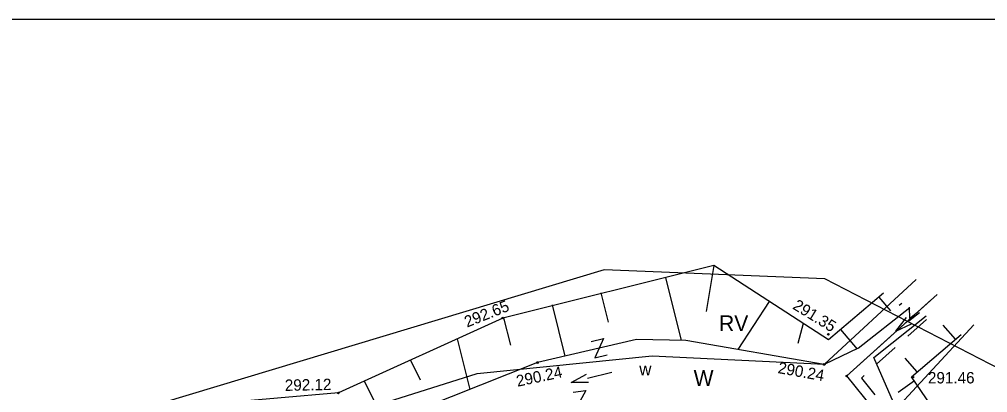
# Model space of a CAD drawing. Extents: x 7477803 to 7478145, y 5500698 to 5500984.
# Drawn here: x 7477935.9 to 7477993.7, y 5500961.3 to 5500983.6 of the extents above; entities that cross this region are included whole.
import ezdxf

# ---------------------------------------------------------------- set-up
doc = ezdxf.new("R2010")
doc.units = 0
for name, color, linetype in [('203-Punkt załamania granicy działki nie stabilizowany', 7, 'Continuous'), ('gr_dzialki', 7, 'Continuous'), ('gr_klasy', 7, 'Continuous'), ('gr_uzytek', 7, 'Continuous'), ('nazwa_cieku', 7, 'Continuous'), ('opis_klasy', 7, 'Continuous'), ('opis_uzytek', 7, 'Continuous'), ('pkt_wys', 7, 'Continuous'), ('pob_gr_obrebu', 7, 'Continuous'), ('przehaczenie', 7, 'Continuous'), ('robocza11', 7, 'Continuous'), ('rzeka', 7, 'Continuous'), ('skarp_wypel', 7, 'Continuous'), ('skarpa_gora', 7, 'Continuous'), ('zakresy', 7, 'Continuous')]:
    doc.layers.add(name, color=color, linetype=linetype)

# ---------------------------------------------------------------- blocks, each defined once
blk = doc.blocks.new('203')
blk.add_circle((0, 0), 0.045)
blk = doc.blocks.new('993')
at = {"layer": 'nazwa_cieku'}
for p, q in [((0, 0), (1.5, 0)), ((1.5, 0.25), (2.5, 0)), ((2.5, 0), (1.5, -0.25))]:
    blk.add_line(p, q, dxfattribs=at)
blk = doc.blocks.new('801_3')
at = {"layer": 'pkt_wys'}
blk.add_circle((0, 0), 0.045, dxfattribs=at)
blk.add_circle((0, 0), 0.045, dxfattribs=at)
blk = doc.blocks.new('801_5')
at = {"layer": 'pkt_wys'}
blk.add_circle((0, 0), 0.05, dxfattribs=at)
blk.add_circle((0, 0), 0.05, dxfattribs=at)
blk = doc.blocks.new('991_5_1')
at = {"layer": 'przehaczenie'}
blk.add_lwpolyline([(-0.38, 0.5), (0.38, 0.5), (-0.38, -0.5), (0.38, -0.5)], dxfattribs=at)

msp = doc.modelspace()

# ---------------------------------------------------------------- linework, layer by layer
at = {"layer": 'gr_dzialki'}
for points in [[(7477990.325, 5500966.847), (7477985.26, 5500962.28)], [(7477986.83, 5500960.33), (7477985.26, 5500962.28)]]:
    msp.add_lwpolyline(points, dxfattribs=at)
at = {"layer": 'gr_klasy'}
for points in [[(7477983.93, 5500962.98), (7477989.394, 5500968.04)], [(7477992.835, 5500965.322), (7477987.47, 5500959.53)], [(7477963.19, 5500962.42), (7477973.64, 5500963.49)], [(7477973.64, 5500963.49), (7477983.93, 5500962.98)], [(7477939.89, 5500955.07), (7477963.19, 5500962.42)]]:
    msp.add_lwpolyline(points, dxfattribs=at)
at = {"layer": 'gr_uzytek'}
msp.add_lwpolyline([(7477986.83, 5500960.33), (7477985.26, 5500962.28), (7477990.655, 5500967.144)], dxfattribs=at)
at = {"layer": 'nazwa_cieku'}
for p, q in [((7477988.182, 5500964.963), (7477988.816, 5500965.776)), ((7477988.97, 5500965.579), (7477989.596, 5500966.069)), ((7477988.182, 5500964.963), (7477989.124, 5500965.382))]:
    msp.add_line(p, q, dxfattribs=at)
at = {"layer": 'pob_gr_obrebu'}
for p, q in [((7477990.013, 5500965.654), (7477988.898, 5500964.65)), ((7477988.155, 5500963.98), (7477987.041, 5500962.976))]:
    msp.add_line(p, q, dxfattribs=at)
msp.add_lwpolyline([(7477986.298, 5500962.306), (7477986.13, 5500962.155), (7477986.928, 5500961.162)], dxfattribs=at)
at = {"layer": 'przehaczenie'}
for points in [[(7477988.382, 5500966.499), (7477988.545, 5500966.628)], [(7477988.989, 5500966.391), (7477989.002, 5500965.715), (7477989.509, 5500966.115)]]:
    msp.add_lwpolyline(points, dxfattribs=at)
at = {"layer": 'robocza11'}
msp.add_lwpolyline([(7478014.996, 5500697.565), (7478144.729, 5500697.565), (7478144.729, 5500983.565), (7477803.256, 5500983.565), (7477803.256, 5500697.565), (7478010.821, 5500697.565)], close=True, dxfattribs=at)
at = {"layer": 'rzeka'}
for points in [[(7477985.943, 5500963.933), (7477989.027, 5500966.371)], [(7477986.866, 5500963.388), (7477989.991, 5500965.859)], [(7477985.943, 5500963.933), (7477983.914, 5500962.968), (7477975.662, 5500964.399), (7477972.702, 5500964.466), (7477966.794, 5500963.08), (7477958.237, 5500959.69)], [(7477990.994, 5500955.223), (7477989.636, 5500957.056), (7477986.866, 5500963.388)]]:
    msp.add_lwpolyline(points, dxfattribs=at)
at = {"layer": 'skarp_wypel'}
for p, q in [((7477977.317, 5500968.871), (7477976.87, 5500966.13)), ((7477974.444, 5500968.156), (7477975.377, 5500964.406)), ((7477970.587, 5500967.249), (7477971.027, 5500965.485)), ((7477980.619, 5500966.734), (7477978.76, 5500963.862)), ((7477987.169, 5500966.987), (7477987.864, 5500966.167)), ((7477967.676, 5500966.523), (7477968.439, 5500963.466)), ((7477964.776, 5500965.751), (7477965.186, 5500964.109)), ((7477982.649, 5500965.421), (7477982.346, 5500964.221)), ((7477984.881, 5500965.046), (7477985.873, 5500963.878)), ((7477991.741, 5500964.467), (7477991.02, 5500965.311)), ((7477961.998, 5500964.496), (7477962.751, 5500961.478)), ((7477989.459, 5500962.519), (7477988.755, 5500963.345)), ((7477959.222, 5500963.23), (7477959.802, 5500962.043)), ((7477956.446, 5500961.964), (7477957.729, 5500959.449)), ((7477989.301, 5500961.982), (7477988.331, 5500961.29))]:
    msp.add_line(p, q, dxfattribs=at)
at = {"layer": 'skarpa_gora'}
for points in [[(7477977.346, 5500968.88), (7477977.317, 5500968.871), (7477964.721, 5500965.737), (7477954.915, 5500961.267), (7477940.364, 5500959.997)], [(7477987.444, 5500967.213), (7477984.171, 5500964.436), (7477977.317, 5500968.871)], [(7477994.964, 5500953.65), (7477989.125, 5500962.227), (7477992.08, 5500964.748)]]:
    msp.add_lwpolyline(points, dxfattribs=at)
at = {"layer": 'zakresy'}
msp.add_lwpolyline([(7477995.059, 5500962.348), (7477983.951, 5500968.084), (7477970.781, 5500968.613), (7477936.09, 5500958.171), (7477930.511, 5500954.336), (7477914.305, 5500958.58), (7477904.32, 5500957.41), (7477897.265, 5500950.868), (7477811.424, 5500829.338), (7477936.003, 5500769.492), (7478008.982, 5500726.585), (7478019.402, 5500721.781), (7478037.95, 5500734.97), (7478039.493, 5500755.094), (7478043.98, 5500765.708), (7478067.545, 5500795.068), (7478092.109, 5500820.25), (7478076.156, 5500837.989), (7478068.105, 5500851.146), (7478061.422, 5500873.298), (7478054.135, 5500876.371), (7478039.669, 5500897.644), (7478026.36, 5500915.23), (7478015.054, 5500927.728)], close=True, dxfattribs=at)

# ---------------------------------------------------------------- block references
at = {"layer": '203-Punkt załamania granicy działki nie stabilizowany'}
msp.add_blockref('203', (7477985.26, 5500962.28), dxfattribs=at)
at = {"layer": 'nazwa_cieku', "rotation": -166.2325062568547}
msp.add_blockref('993', (7477971.238, 5500962.493), dxfattribs=at)
at = {"layer": 'pkt_wys', "rotation": 0.0626175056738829}
for name, p in [('801_5', (7477964.721, 5500965.737)), ('801_5', (7477984.162, 5500964.769)), ('801_5', (7477966.794, 5500963.08)), ('801_5', (7477983.914, 5500962.968)), ('801_3', (7477989.214, 5500962.214)), ('801_5', (7477954.915, 5500961.267))]:
    msp.add_blockref(name, p, dxfattribs=at)
at = {"layer": 'przehaczenie'}
for p, rotation in [((7477970.482, 5500963.945), 13.205833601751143), ((7477969.387, 5500960.868), 8.793636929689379)]:
    msp.add_blockref('991_5_1', p, dxfattribs=dict(at, rotation=rotation))

# ---------------------------------------------------------------- texts
at = {"layer": 'nazwa_cieku'}
msp.add_text('w', height=0.75, rotation=0.06262, dxfattribs=at).set_placement((7477972.876, 5500962.31))
at = {"layer": 'opis_klasy'}
msp.add_text('RV', height=0.94, dxfattribs=at).set_placement((7477977.636, 5500964.958))
at = {"layer": 'opis_uzytek'}
msp.add_text('W', height=0.94, dxfattribs=at).set_placement((7477976.121, 5500961.688))
at = {"layer": 'pkt_wys'}
for s, rotation, p in [('292.65', 21.78026, (7477962.596, 5500965.164)), ('291.35', 328.55835, (7477981.981, 5500966.318)), ('290.24', 11.93647, (7477965.608, 5500961.632)), ('290.24', 349.75777, (7477981.112, 5500962.457)), ('292.12', 1.13679, (7477951.724, 5500961.386)), ('291.46', 0.06262, (7477990.107, 5500961.832))]:
    msp.add_text(s, height=0.68, rotation=rotation, dxfattribs=at).set_placement(p)

doc.saveas('drawing.dxf')
